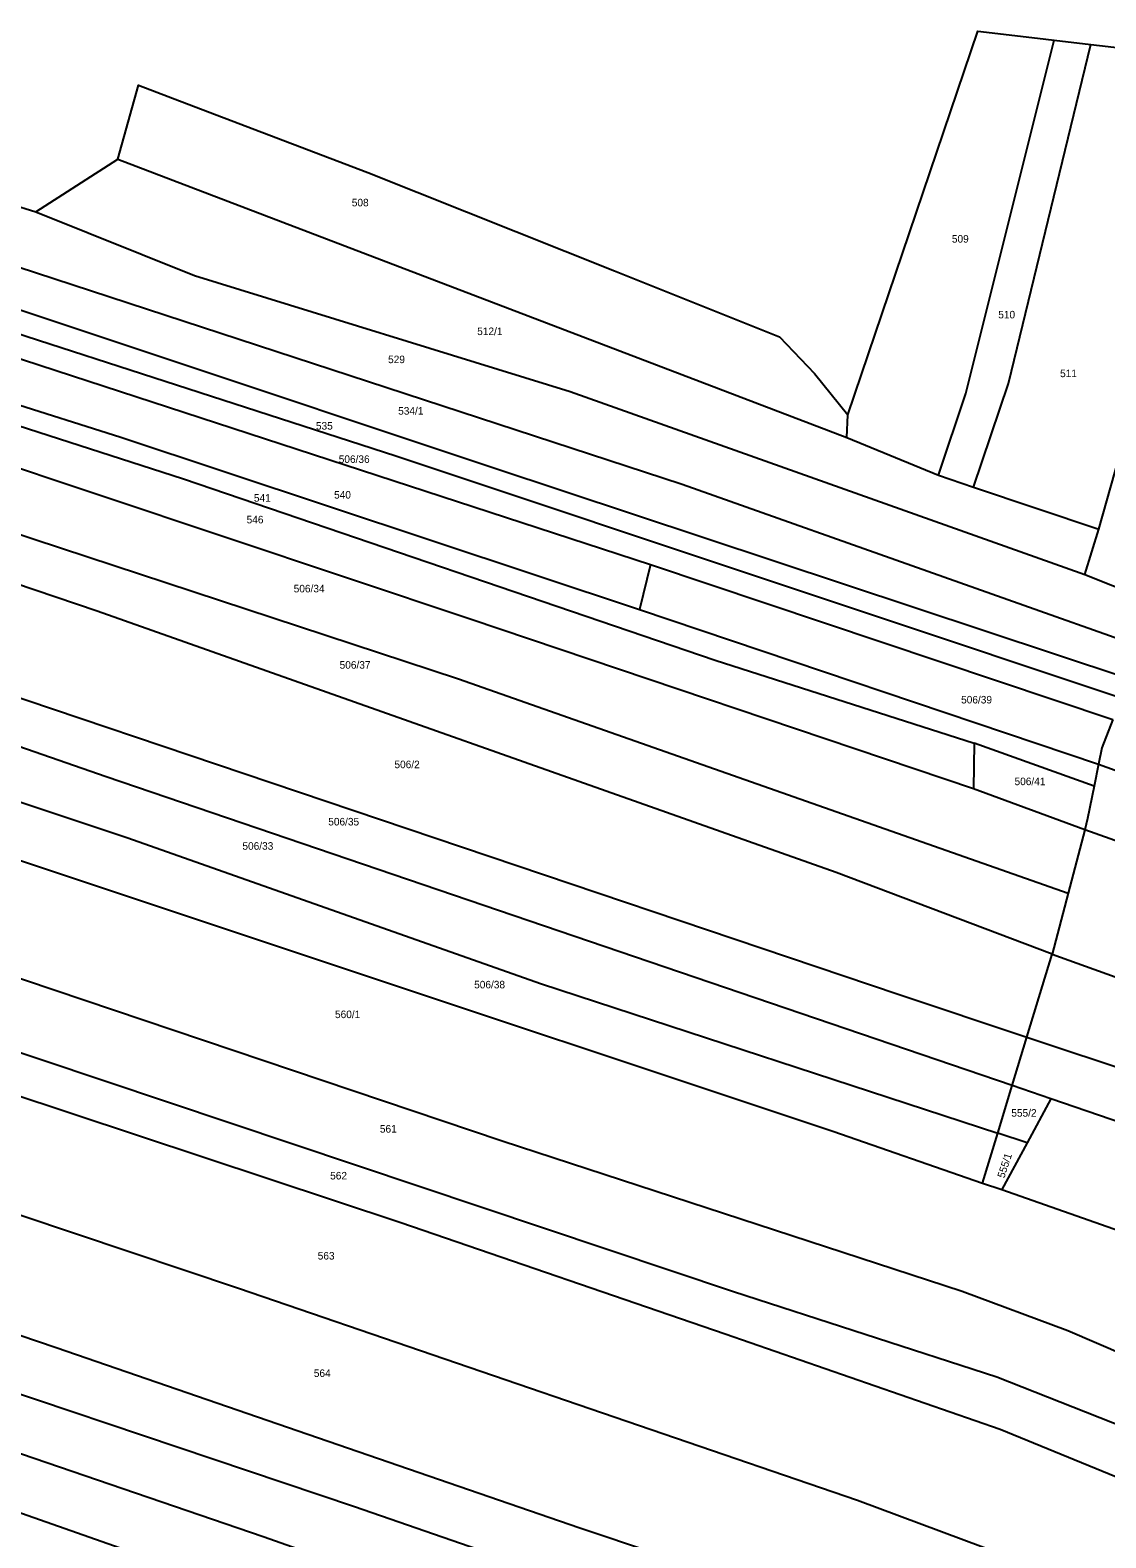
# Model space of a CAD drawing. Extents: x -744566 to -741843, y -1128407 to -1126744.
# Drawn here: x -742310.3 to -742068.2, y -1127136.3 to -1126796.9 of the extents above; entities that cross this region are included whole.
import ezdxf

# ---------------------------------------------------------------- set-up
doc = ezdxf.new("R2010")
doc.units = 0
doc.layers.add('Hranice parcel', color=7, linetype='Continuous')
doc.layers.add('Parcelní čísla', color=7, linetype='Continuous')

msp = doc.modelspace()

# ---------------------------------------------------------------- linework, layer by layer
at = {"layer": 'Hranice parcel'}
for p, q in [((-742079.82, -1126799.1), (-742071.61, -1126800.06)), ((-742309.03, -1126837.78), (-742290.61, -1126825.94)), ((-742290.61, -1126825.94), (-742126.53, -1126888.57)), ((-742234.35, -1126828.88), (-742178.83, -1126851.05)), ((-742126.53, -1126888.57), (-742126.31, -1126883.51)), ((-742126.53, -1126888.57), (-742105.89, -1126897.09)), ((-742105.89, -1126897.09), (-742097.97, -1126899.78)), ((-742097.97, -1126899.78), (-742069.77, -1126909.24)), ((-742072.95, -1126919.43), (-742069.77, -1126909.24)), ((-742170.7, -1126917.2), (-742173.2, -1126927.29)), ((-742170.7, -1126917.2), (-742066.64, -1126952.09)), ((-742072.95, -1126919.43), (-742042.16, -1126931.63)), ((-742173.2, -1126927.29), (-742069.84, -1126962.11)), ((-742097.85, -1126957.39), (-742097.97, -1126967.72)), ((-742070.84, -1126967.09), (-742097.85, -1126957.39)), ((-742069.84, -1126962.11), (-742070.84, -1126967.09)), ((-742069.84, -1126962.11), (-741894.54, -1127025.39)), ((-742072.97, -1126976.88), (-742097.97, -1126967.72)), ((-742072.97, -1126976.88), (-742076.69, -1126991.19)), ((-742031.04, -1126992.02), (-742072.97, -1126976.88)), ((-742076.69, -1126991.19), (-742080.25, -1127004.92)), ((-742085.96, -1127023.63), (-742080.25, -1127004.92)), ((-742080.25, -1127004.92), (-742044.21, -1127017.99)), ((-742089.28, -1127034.5), (-742085.96, -1127023.63)), ((-742085.96, -1127023.63), (-741952.12, -1127068.07)), ((-742092.54, -1127045.19), (-742089.28, -1127034.5)), ((-742080.56, -1127037.47), (-742089.28, -1127034.5)), ((-742080.56, -1127037.47), (-742085.92, -1127047.36)), ((-742095.98, -1127056.46), (-742092.54, -1127045.19)), ((-742085.92, -1127047.36), (-742092.54, -1127045.19)), ((-742085.92, -1127047.36), (-742091.61, -1127057.86)), ((-742095.98, -1127056.46), (-742091.61, -1127057.86))]:
    msp.add_line(p, q, dxfattribs=at)
for points in [[(-742430.18, -1126796.86), (-742427.9, -1126797.45), (-742403.35, -1126806.76), (-742376.71, -1126816.86), (-742348.55, -1126825.56), (-742320.68, -1126834.18), (-742309.03, -1126837.78)], [(-742126.31, -1126883.51), (-742097.03, -1126797.08), (-742083.58, -1126798.66), (-742079.82, -1126799.1)], [(-742105.89, -1126897.09), (-742099.72, -1126878.68), (-742079.82, -1126799.1)], [(-742097.97, -1126899.78), (-742090.09, -1126876.39), (-742071.61, -1126800.06)], [(-742071.61, -1126800.06), (-742057.34, -1126801.74), (-742042.45, -1126803.48)], [(-742069.77, -1126909.24), (-742059.79, -1126873.9), (-742052.88, -1126842.88), (-742042.45, -1126803.48)], [(-742434.93, -1126808.05), (-742383.95, -1126826.97), (-742163.59, -1126899.11), (-742045.77, -1126940.83)], [(-742290.61, -1126825.94), (-742285.95, -1126809.25), (-742275.12, -1126813.37), (-742234.35, -1126828.88)], [(-742438.82, -1126815.98), (-742394.95, -1126832.23), (-742364.36, -1126842.59), (-742205.97, -1126895.42), (-742047.88, -1126947.84)], [(-742047.88, -1126947.84), (-742049.19, -1126952.47), (-742228, -1126892.81), (-742365.77, -1126848.2), (-742441.29, -1126821.14)], [(-742443.9, -1126826.23), (-742405.75, -1126840.23), (-742380.59, -1126848.67), (-742170.7, -1126917.2)], [(-742448.41, -1126835.02), (-742368.08, -1126863.73), (-742289.94, -1126888.49), (-742173.2, -1126927.29)], [(-742451.1, -1126839.6), (-742404.27, -1126856.43), (-742275.83, -1126897.91), (-742156.13, -1126938.74), (-742097.85, -1126957.39)], [(-742309.03, -1126837.78), (-742273.34, -1126852.11), (-742188.78, -1126878.23), (-742072.95, -1126919.43)], [(-742097.97, -1126967.72), (-742211.09, -1126929.59), (-742350.35, -1126883.06), (-742455.11, -1126846.76)], [(-742178.83, -1126851.05), (-742141.64, -1126865.9), (-742133.75, -1126874.2), (-742126.31, -1126883.51)], [(-742461.67, -1126859.1), (-742417.12, -1126876.07), (-742213.93, -1126942.95), (-742076.69, -1126991.19)], [(-742080.25, -1127004.92), (-742128.87, -1126986.52), (-742295.26, -1126927.65), (-742383.7, -1126897.74), (-742465.86, -1126866.52)], [(-742477.38, -1126887.58), (-742416.04, -1126911.9), (-742348.05, -1126935.25), (-742114.93, -1127013.93), (-742085.96, -1127023.63)], [(-742089.28, -1127034.5), (-742293.25, -1126965), (-742398.92, -1126928.26), (-742481.95, -1126896.36)], [(-742486.79, -1126907.12), (-742444.87, -1126924.33), (-742397.83, -1126942.23), (-742288.59, -1126978.66), (-742195.26, -1127011.61), (-742092.54, -1127045.19)], [(-742492.57, -1126918.49), (-742455.79, -1126933.86), (-742390.03, -1126957.98), (-742252.16, -1127003.9), (-742129.68, -1127044.77), (-742095.98, -1127056.46)], [(-742504.35, -1126941.71), (-742474.75, -1126953.67), (-742378.88, -1126988.04), (-742204.08, -1127046.96), (-742100.58, -1127080.82), (-742076.73, -1127089.67), (-742044, -1127103.72)], [(-742066.64, -1126952.09), (-742069.11, -1126958.48), (-742069.84, -1126962.11)], [(-742512.02, -1126957.27), (-742426.6, -1126987.75), (-742322.02, -1127023.9), (-742152.02, -1127080.85), (-742092.77, -1127100.11), (-742049.6, -1127117.15)], [(-742516.09, -1126965.6), (-742463.84, -1126985.43), (-742374.91, -1127016.27), (-742226.88, -1127065.31), (-742153.9, -1127090.43), (-742091.98, -1127111.83), (-742053.72, -1127127.51)], [(-742070.84, -1126967.09), (-742072.31, -1126974.35), (-742072.97, -1126976.88)], [(-742527.24, -1126986.86), (-742482.52, -1127005.44), (-742410.26, -1127030.86), (-742263.45, -1127080.11), (-742124.08, -1127127.86), (-742062.93, -1127150.64)], [(-742540.51, -1127007.89), (-742508.14, -1127021.79), (-742465.67, -1127038.76), (-742304.51, -1127093.48), (-742186.57, -1127134.04), (-742101.64, -1127162.49), (-742071.1, -1127173.63)], [(-742548.14, -1127019.47), (-742535.36, -1127026.31), (-742485.61, -1127044.66), (-742396.17, -1127075.85), (-742237.29, -1127129.3), (-742102.44, -1127175.98), (-742075.64, -1127186.64)], [(-742556.03, -1127030.18), (-742540.54, -1127037.88), (-742464.14, -1127065.48), (-742257.87, -1127136.04), (-742181.95, -1127162.82), (-742111.16, -1127186.39), (-742079.42, -1127198.6)], [(-742081.6, -1127209.14), (-742129.12, -1127193.01), (-742202.75, -1127169.34), (-742345.7, -1127119.16), (-742474.83, -1127076.87), (-742507.28, -1127063.47), (-742545.28, -1127047.75), (-742563.37, -1127039.11)], [(-741935.95, -1127085.33), (-742053.68, -1127046.69), (-742080.56, -1127037.47)], [(-742091.61, -1127057.86), (-742033.08, -1127078.43), (-742033.9, -1127081.06)]]:
    msp.add_lwpolyline(points, dxfattribs=at)

# ---------------------------------------------------------------- texts
at = {"layer": 'Parcelní čísla'}
for s, p in [('508', (-742237.93, -1126836.53)), ('509', (-742102.86, -1126844.7)), ('510', (-742092.42, -1126861.76)), ('512/1', (-742209.7, -1126865.52)), ('529', (-742229.76, -1126871.84)), ('511', (-742078.5, -1126874.99)), ('534/1', (-742227.5, -1126883.43)), ('535', (-742246.01, -1126886.8)), ('506/36', (-742240.87, -1126894.3)), ('540', (-742241.92, -1126902.33)), ('541', (-742259.97, -1126903.03)), ('546', (-742261.6, -1126907.91)), ('506/34', (-742251.01, -1126923.45)), ('506/37', (-742240.67, -1126940.63)), ('506/39', (-742100.78, -1126948.46)), ('506/2', (-742228.33, -1126963.04)), ('506/41', (-742088.75, -1126966.86)), ('506/35', (-742243.23, -1126975.93)), ('506/33', (-742262.55, -1126981.4)), ('506/38', (-742210.39, -1127012.61)), ('560/1', (-742241.71, -1127019.31)), ('555/2', (-742089.48, -1127041.5)), ('561', (-742231.61, -1127045.09)), ('562', (-742242.8, -1127055.64)), ('563', (-742245.6, -1127073.67)), ('564', (-742246.48, -1127100.1))]:
    msp.add_text(s, height=1.7, dxfattribs=at).set_placement(p)
msp.add_text('555/1', height=1.7, rotation=72, dxfattribs=at).set_placement((-742091.061, -1127055.462))

doc.saveas('drawing.dxf')
